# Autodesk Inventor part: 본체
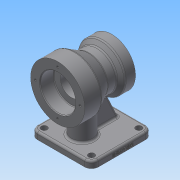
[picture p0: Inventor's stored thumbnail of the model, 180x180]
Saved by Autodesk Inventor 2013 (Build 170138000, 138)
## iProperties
Created: 2019-01
Part Number: 본체
Material: 일반
Document SubType Name: Modeling
Designer: Administrator
Density: 1 g/cm^3
Author: Administrator
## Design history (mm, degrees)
sketch "스케치1"
  geometry: L1 (0, 26)-(0, 40); L2 (0, 40)-(25, 40); L3 (25, 40)-(45.785, 28); L4 (45.785, 28)-(59.126, 28); L5 (59.126, 28)-(65, 35); L6 (65, 35)-(80, 35); L7 (80, 35)-(80, 20); L8 (80, 20)-(63, 20); L9 (63, 20)-(63, 16); L10 (63, 16)-(20, 16); L11 (20, 16)-(20, 26); L12 (20, 26)-(0, 26); L13 (0, 0)-(80, 0)
  constraints: 26 end point, 8 parallel, 2 perpendicular, 2 point on line, 1 vertical
  dimensions: "d0" = 25 distance of L1.end L2.end; "d2" = 15 distance of L5.end L6.end; "d4" = 52 diameter of L12 L13; "d5" = 32 diameter of L10 L13; "d6" = 40 diameter of L8 L13; "d7" = 56 diameter of L4 L13; "d8" = 70 diameter of L6 L13; "d9" = 80 diameter of L2 L13; "d10" = 80 distance between parallel lines of L7 L1; "d11" = 20 distance of L11.end L1.start; "d12" = 17 distance of L7.end L8.end; "d13" = 30 deg angle of L3 L4; "d14" = 50 deg angle of L4 L5
revolve "회전1" sketch "스케치1" stored, may be unused: angle "d15" = 90 deg
node "작업 평면1"
sketch "스케치2"
  geometry: L1 (-5, 45)-(-95, 45); L2 (-95, 45)-(-95, -45); L3 (-95, -45)-(-5, -45); L4 (-5, -45)-(-5, 45); L5 (-5, 45)-(-95, -45); L6 (-95, 45)-(-5, -45); L7 (0, 40)-(0, -40) reference; 4 further points
  constraints: 12 end point, 4 midpoint, 2 parallel, 1 horizontal, 1 horizontal alignment, 1 perpendicular
  dimensions: "d17" = 90 distance of L3.end L2.end; "d18" = 90 distance of L2.end L1.end; "d19" = 5 distance from line of L1.start L7
extrude "돌출1" join sketch "스케치2" distance "d20" = 10; taper "d21" = 0 deg
sketch "스케치3"
  geometry: L1 (5, 45)-(5, -45) reference; C1 r 16 at (35, -1); 1 further point
  constraints: 1 centre point
  dimensions: "d22" = 16 radius of C1; "d23" = 30 distance from line of L1 C1.centre; "d24" = 46 vertical distance of L1.start C1.centre
extrude "돌출2" join sketch "스케치3" stored distance "d25" = 10; taper "d26" = 0 deg
sketch "스케치4"
  geometry: L1 (51, -70)-(51, -27.982) reference; L2 (95, -70)-(5, -70) reference; L3 (50.969, -28)-(59.126, -28) reference; L4 (59.126, -28)-(65, -35) reference; L5 (68.679, -35)-(85, -70); L6 (95, -80)-(95, -70) reference; L7 (65, -35)-(80, -35) reference; 1 further point
  constraints: 2 end point, 2 point on line
  dimensions: "d27" = 25 deg angle of L5 L6; "d28" = 10 distance of L2.start L5.end
feature "리브1" sketch "스케치4" dims "d29" = 1, "d30" = 10, "d31" = 0, "d32" = 0, "d33" = 1, "d34" = 1
sketch "스케치5"
  geometry: C1 r 16 at (0, 0) reference; 2 further points
  constraints: 1 vertical alignment
  dimensions: "d35" = 33 distance of point (0, 0) point (0, 33)
hole "구멍1" sketch "스케치5" at (0, 33) diameter "d36" = 3.242; stored, may be unused: countersink angle "d40" = 90 deg, drill point angle "d42" = 118 deg; dims "d37" = 9, "d38" = 4, "d39" = 2, "d41" = 11
sketch "스케치6"
  geometry: C1 r 35 at (0, 0) reference; 2 further points
  constraints: 1 vertical alignment
  dimensions: "d46" = 27.5 distance of point (0, 27.5) point (0, 0)
hole "구멍2" sketch "스케치6" at (0, 27.5) diameter "d47" = 3.242; stored, may be unused: countersink angle "d51" = 90 deg, drill point angle "d53" = 118 deg; dims "d48" = 9, "d49" = 4, "d50" = 2, "d52" = 11
fillet "모깎기1" dims "d57" = 10
sketch "스케치7"
  geometry: L1 (95, -35)-(95, 35) reference; L2 (15, -45)-(85, -45) reference; L3 (5, 35)-(5, -35) reference; L4 (85, 45)-(15, 45) reference; A1 r 10 centre (85, 35) between (95, 35) and (85, 45) reference; A2 r 10 centre (85, -35) between (85, -45) and (95, -35) reference; A3 r 10 centre (15, -35) between (5, -35) and (15, -45) reference; A4 r 10 centre (15, 35) between (15, 45) and (5, 35) reference; 5 further points
  constraints: 4 coincident
hole "구멍3" sketch "스케치7" at (15, 35), (85, 35), (85, -35), (15, -35) diameter "d58" = 9; stored, may be unused: countersink angle "d62" = 90 deg, drill point angle "d64" = 0 deg; dims "d59" = 9, "d60" = 4, "d61" = 2, "d63" = 11
node "작업 평면2"
sketch "스케치8"
  geometry: L1 (5, -70)-(5, -80) reference; 2 further points
  constraints: 1 other
  dimensions: "d66" = 46 distance from line of L1 point (51, -76); "d67" = 4 vertical distance of L1.end point (51, -76)
feature "엠보싱1" sketch "스케치8" dims "d0" = 25, "d2" = 15, "d4" = 52, "d5" = 32, "d6" = 40, "d7" = 56, "d8" = 70, "d9" = 80, "d10" = 80, "d11" = 20, "d12" = 17, "d13" = 30 deg, "d14" = 50 deg, "d17" = 90, "d68" = 0.5, "d69" = 0
fillet "모깎기2" dims "d70" = 3
fillet "모깎기3" dims "d71" = 3
fillet "모깎기4" dims "d72" = 1
fillet "모깎기5" dims "d73" = 0.6
chamfer "모따기1" distance "d74" = 1; stored, may be unused: second distance "d75" = 2, angle "d76" = 45 deg
node "솔리드1"
pattern_circular "원형 패턴1" dims angle "d44" = 360 deg
pattern_circular "원형 패턴2" dims angle "d55" = 360 deg
node "투영된 루프1"
other parameters: "d65" = 89
